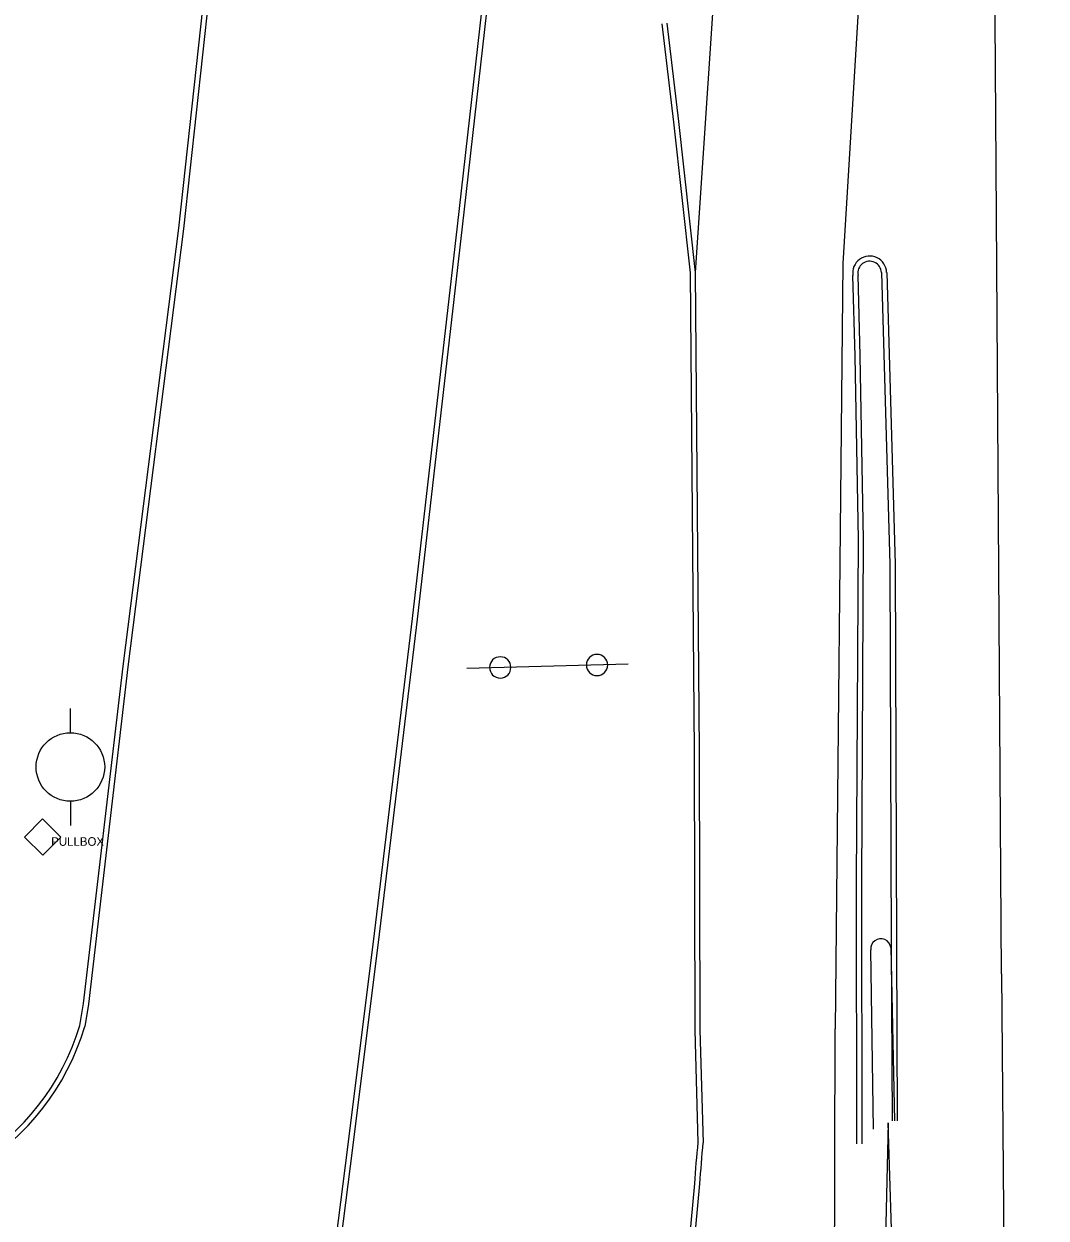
# Model space of a CAD drawing. Extents: x 2145380 to 2156929, y 139568 to 149130.
# Drawn here: x 2150658.7 to 2150778, y 143857.7 to 143997 of the extents above; entities that cross this region are included whole.
import ezdxf

# ---------------------------------------------------------------- set-up
doc = ezdxf.new("R2010")
doc.units = 0
for name, color, linetype in [('Default', 7, 'Continuous'), ('TOPO_Asphalt', 7, 'Continuous'), ('TOPO_Curb Back', 7, 'Continuous'), ('TOPO_Guardrail', 7, 'Continuous'), ('TOPO_Misc', 7, 'Continuous'), ('TOPO_Power Pole', 7, 'Continuous'), ('TOPO_Power Pullbox', 7, 'Continuous'), ('TOPO_Sign', 7, 'Continuous'), ('TOPO_Wall Freestanding', 7, 'Continuous')]:
    doc.layers.add(name, color=color, linetype=linetype)

# ---------------------------------------------------------------- blocks, each defined once
blk = doc.blocks.new('POST')
at = {"layer": 'TOPO_Misc'}
for start, end in [(90, 180), (180, 270), (360, 90), (270, 0)]:
    blk.add_arc((-0.01, 0.03), 3.16, start, end, dxfattribs=at)
blk = doc.blocks.new('POWPOL')
at = {"layer": 'TOPO_Power Pole'}
for p, q in [((0, 10.16), (0, 17.34)), ((0, -10.16), (0, -17.34))]:
    blk.add_line(p, q, dxfattribs=at)
blk.add_circle((0, 0), 10.16, dxfattribs=at)
blk = doc.blocks.new('pulbox')
at = {"layer": 'Default'}
blk.add_lwpolyline([(-5.38, -0.01), (-0.02, 5.42), (5.4, 0.06), (0.05, -5.36), (-5.38, -0.01)], dxfattribs=at)
blk.add_text('PULLBOX', height=2.54, dxfattribs=at).set_placement((2.54, -2.54))

msp = doc.modelspace()

# ---------------------------------------------------------------- linework, layer by layer
at = {"layer": 'TOPO_Asphalt'}
for points in [[(2150756.81, 144355.63), (2150753.8, 144289.36), (2150751.49, 144221.78), (2150747.14, 144143.49), (2150742.96, 144055.79), (2150737.09, 143968.03)], [(2150772.83, 143886.17), (2150772.19, 143980.5), (2150771.59, 144071.71), (2150770.85, 144158.43), (2150770.17, 144256.18), (2150764.43, 144153.13), (2150758.98, 144046.02), (2150754.32, 143969.07), (2150753.42, 143879.74)], [(2150772.83, 143886.16), (2150773.51, 143803.73), (2150773.92, 143723.32), (2150774.62, 143621.07), (2150775.2, 143512.02), (2150776.06, 143373.6), (2150776.8, 143240.22), (2150777.68, 143101.35), (2150778.04, 143055.61)], [(2150761.33, 143058.39), (2150760.85, 143109.01), (2150759.25, 143261.24), (2150757.66, 143398.88), (2150755.78, 143565.43), (2150754.21, 143703.67), (2150753.32, 143849.02), (2150753.42, 143879.74)]]:
    msp.add_lwpolyline(points, dxfattribs=at)
at = {"layer": 'TOPO_Curb Back'}
for points in [[(2150681.26, 143761.28), (2150688.25, 143800.82), (2150696.26, 143863.82), (2150699.51, 143889.9), (2150704.08, 143927.64), (2150709.32, 143973.42), (2150713.36, 144009.22), (2150716.29, 144039.49), (2150720.45, 144094.42), (2150723.05, 144142.66), (2150724.57, 144175.07), (2150725.79, 144212.36), (2150726.43, 144252.04), (2150727.32, 144302.08), (2150727.39, 144340.7), (2150727.51, 144356.42), (2150726.94, 144419.58), (2150726.03, 144497.06)], [(2150681.85, 143761.17), (2150688.84, 143800.73), (2150696.86, 143863.74), (2150700.1, 143889.83), (2150704.68, 143927.57), (2150709.91, 143973.35), (2150713.96, 144009.16), (2150716.89, 144039.44), (2150721.04, 144094.38), (2150723.65, 144142.63), (2150725.16, 144175.04), (2150726.39, 144212.35), (2150727.03, 144252.03), (2150727.92, 144302.07), (2150727.99, 144340.7), (2150728.11, 144356.42), (2150727.54, 144419.59), (2150726.63, 144497.07)], [(2150692.95, 144194.83), (2150691.08, 144156.61), (2150686.94, 144086.01), (2150682.68, 144027.38), (2150676.75, 143973.2), (2150670.26, 143922.08), (2150665.65, 143882.73), (2150665.23, 143880.15)], [(2150693.54, 144194.77), (2150691.68, 144156.58), (2150687.54, 144085.97), (2150683.27, 144027.33), (2150677.35, 143973.13), (2150670.85, 143922.01), (2150666.25, 143882.65), (2150665.82, 143880.02)], [(2150733.18, 143997.05), (2150734.53, 143985.57), (2150736.49, 143967.99), (2150736.95, 143912.1), (2150737.03, 143879.62), (2150737.39, 143866.49)], [(2150733.77, 143997.12), (2150735.12, 143985.64), (2150737.09, 143968.03), (2150737.55, 143912.11), (2150737.63, 143879.63), (2150737.99, 143866.47)], [(2150755.95, 143866.33), (2150755.92, 143896.82), (2150756.12, 143936.85), (2150755.73, 143958.27), (2150755.48, 143967.68)], [(2150756.55, 143866.33), (2150756.52, 143896.82), (2150756.72, 143936.86), (2150756.33, 143958.29), (2150756.08, 143967.73)], [(2150758.83, 143968.02), (2150759.8, 143933.98), (2150759.96, 143889.46), (2150760.05, 143869)], [(2150759.43, 143968.04), (2150760.4, 143933.99), (2150760.56, 143889.46), (2150760.65, 143869.01)], [(2150736.99, 143861.71), (2150734.5, 143834.78), (2150731.81, 143811.32)], [(2150737.59, 143861.66), (2150735.1, 143834.72), (2150732.41, 143811.24)]]:
    msp.add_lwpolyline(points, dxfattribs=at)
for centre, radius, start, end in [((2150757.44, 143967.97), 1.98, 1.9911, 188.5491), ((2150757.44, 143967.97), 1.38, 2.0591, 189.9391), ((2150638.15, 143888.23), 28.87, 259.1877, 343.4724), ((2150638.15, 143888.23), 28.27, 259.2106, 343.395), ((2150863.4, 143853.72), 126.66, 174.2135, 176.3843), ((2150863.57, 143853.71), 126.23, 174.1982, 176.3876)]:
    msp.add_arc(centre, radius, start, end, dxfattribs=at)
at = {"layer": 'TOPO_Guardrail'}
for points in [[(2150757.9, 143868.06), (2150757.58, 143888.97)], [(2150759.91, 143889.24), (2150760.35, 143869.01)]]:
    msp.add_lwpolyline(points, dxfattribs=at)
msp.add_arc((2150758.74, 143889.11), 1.17, 6.2021, 187.1807, dxfattribs=at)
at = {"layer": 'TOPO_Sign'}
msp.add_lwpolyline([(2150729.27, 143922.3), (2150710.41, 143921.82)], dxfattribs=at)
at = {"layer": 'TOPO_Wall Freestanding'}
msp.add_lwpolyline([(2150769.17, 143080.78), (2150767.89, 143167.61), (2150765.93, 143268.98), (2150763.03, 143421.04), (2150761.46, 143572.97), (2150760.66, 143679.73), (2150760.43, 143710.32), (2150760.15, 143764.69), (2150761.19, 143799.86), (2150760.93, 143826.74), (2150759.61, 143868.78), (2150758.64, 143826.63), (2150758.62, 143806.22), (2150758.7, 143793.94), (2150760.2, 143754.59)], dxfattribs=at)

# ---------------------------------------------------------------- block references
at = {"layer": 'TOPO_Misc', "xscale": 0.39370000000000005, "yscale": 0.3937000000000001}
for p in [(2150714.32, 143921.92), (2150725.62, 143922.21)]:
    msp.add_blockref('POST', p, dxfattribs=at)
at = {"layer": 'TOPO_Power Pole', "xscale": 0.39370000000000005, "yscale": 0.3937000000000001}
msp.add_blockref('POWPOL', (2150664.15, 143910.32), dxfattribs=at)
at = {"layer": 'TOPO_Power Pullbox', "xscale": 0.39370000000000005, "yscale": 0.3937000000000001}
msp.add_blockref('pulbox', (2150660.91, 143902.12), dxfattribs=at)

doc.saveas('drawing.dxf')
